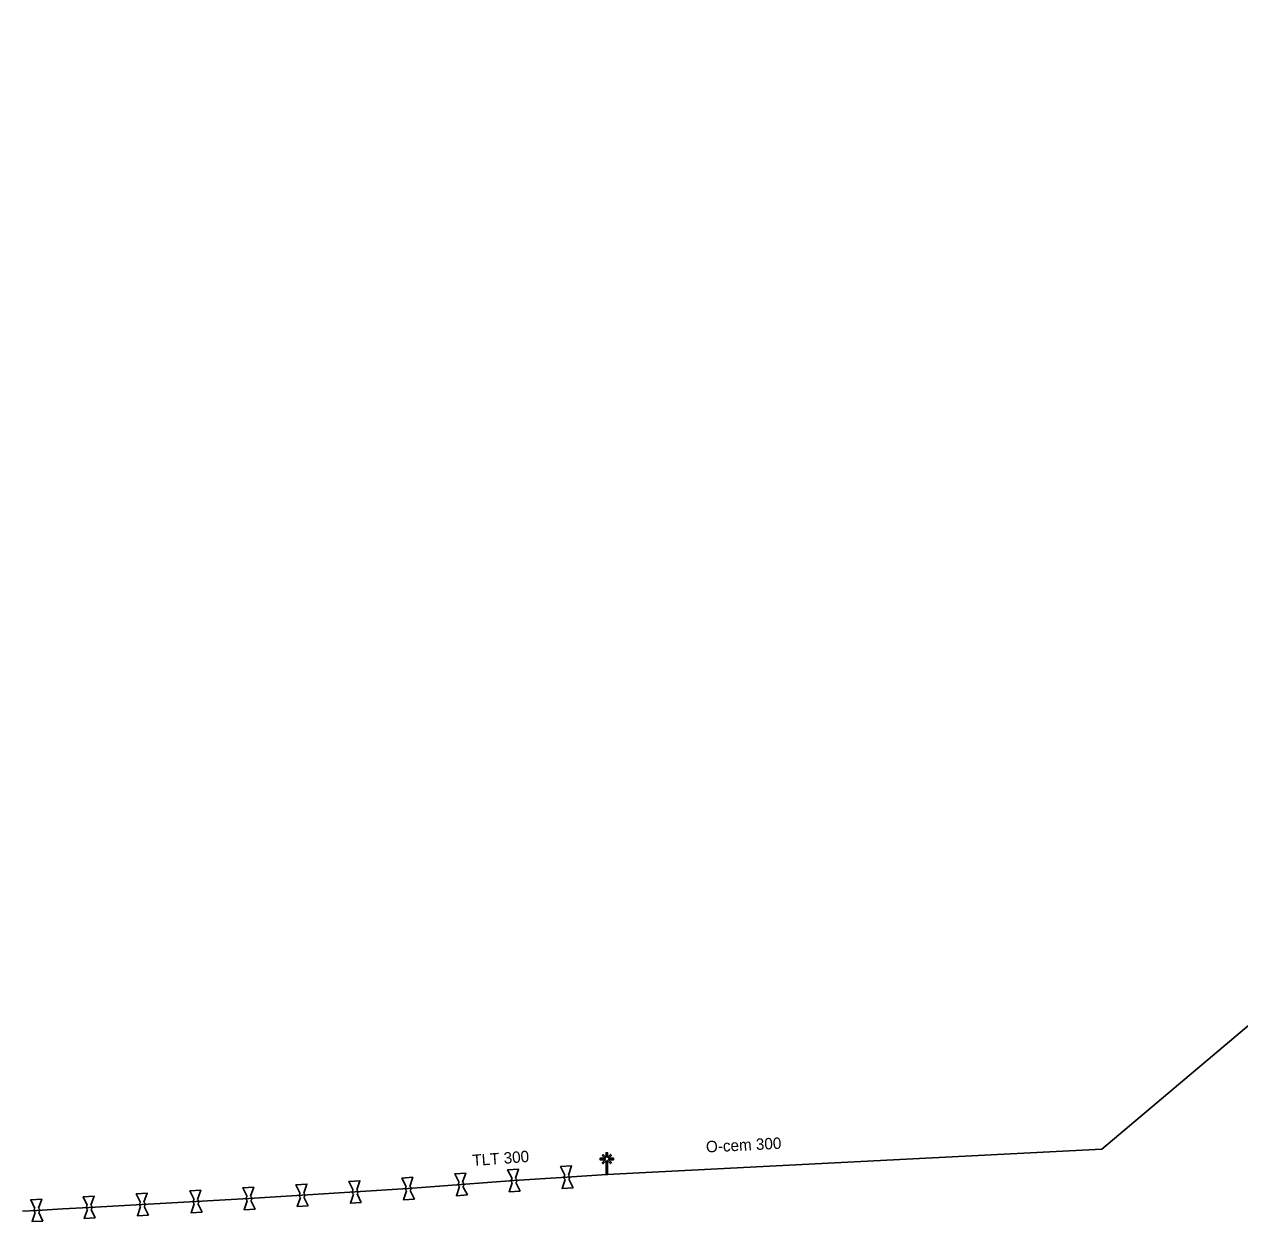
# Model space of a CAD drawing. Extents: x -638315 to -636370, y -1116147 to -1115110.
# Drawn here: x -636990.8 to -636852.3, y -1116147.3 to -1116010.8 of the extents above; entities that cross this region are included whole.
import ezdxf

# ---------------------------------------------------------------- set-up
doc = ezdxf.new("R2010")
doc.units = 0
for name, color, linetype in [('Default', 7, 'Continuous'), ('VP Lomový bod', 7, 'Continuous'), ('VP Změna materiálu', 7, 'Continuous'), ('VP Řad', 7, 'Continuous'), ('VP Řad - popis', 7, 'Continuous')]:
    doc.layers.add(name, color=color, linetype=linetype)

msp = doc.modelspace()

# ---------------------------------------------------------------- linework, layer by layer
at = {"layer": 'Default'}
for points in [[(-636941.24, -1116143.26), (-636941.28, -1116143.23), (-636941.31, -1116143.19), (-636941.36, -1116143.12), (-636941.36, -1116143.03), (-636941.37, -1116142.95), (-636941.33, -1116142.88), (-636941.31, -1116142.83), (-636941.27, -1116142.79)], [(-636940.87, -1116142.76), (-636940.82, -1116142.79), (-636940.79, -1116142.83), (-636940.75, -1116142.9), (-636940.74, -1116142.99), (-636940.73, -1116143.07), (-636940.77, -1116143.15), (-636940.79, -1116143.19), (-636940.83, -1116143.23)], [(-636935.21, -1116142.81), (-636935.25, -1116142.78), (-636935.28, -1116142.74), (-636935.33, -1116142.66), (-636935.33, -1116142.58), (-636935.34, -1116142.5), (-636935.3, -1116142.43), (-636935.28, -1116142.38), (-636935.24, -1116142.34)], [(-636934.83, -1116142.31), (-636934.79, -1116142.34), (-636934.76, -1116142.39), (-636934.71, -1116142.46), (-636934.71, -1116142.54), (-636934.7, -1116142.62), (-636934.74, -1116142.7), (-636934.76, -1116142.75), (-636934.8, -1116142.78)], [(-636929.19, -1116142.44), (-636929.23, -1116142.41), (-636929.26, -1116142.36), (-636929.31, -1116142.29), (-636929.31, -1116142.21), (-636929.32, -1116142.13), (-636929.28, -1116142.05), (-636929.26, -1116142), (-636929.22, -1116141.97)], [(-636928.81, -1116141.94), (-636928.77, -1116141.97), (-636928.74, -1116142.02), (-636928.69, -1116142.09), (-636928.69, -1116142.17), (-636928.68, -1116142.25), (-636928.72, -1116142.33), (-636928.74, -1116142.38), (-636928.78, -1116142.41)], [(-636965.42, -1116144.86), (-636965.46, -1116144.83), (-636965.49, -1116144.78), (-636965.54, -1116144.71), (-636965.54, -1116144.63), (-636965.55, -1116144.55), (-636965.51, -1116144.47), (-636965.49, -1116144.42), (-636965.45, -1116144.39)], [(-636965.04, -1116144.36), (-636965, -1116144.39), (-636964.97, -1116144.44), (-636964.92, -1116144.51), (-636964.92, -1116144.59), (-636964.91, -1116144.67), (-636964.95, -1116144.75), (-636964.97, -1116144.8), (-636965.01, -1116144.84)], [(-636959.37, -1116144.5), (-636959.41, -1116144.47), (-636959.44, -1116144.42), (-636959.49, -1116144.35), (-636959.49, -1116144.27), (-636959.5, -1116144.19), (-636959.46, -1116144.11), (-636959.44, -1116144.06), (-636959.4, -1116144.03)], [(-636958.99, -1116144), (-636958.95, -1116144.03), (-636958.92, -1116144.08), (-636958.87, -1116144.15), (-636958.87, -1116144.23), (-636958.86, -1116144.31), (-636958.9, -1116144.39), (-636958.92, -1116144.44), (-636958.96, -1116144.47)], [(-636953.32, -1116144.12), (-636953.36, -1116144.09), (-636953.39, -1116144.04), (-636953.44, -1116143.97), (-636953.44, -1116143.89), (-636953.45, -1116143.81), (-636953.41, -1116143.73), (-636953.39, -1116143.68), (-636953.35, -1116143.65)], [(-636952.94, -1116143.62), (-636952.9, -1116143.65), (-636952.87, -1116143.7), (-636952.82, -1116143.77), (-636952.82, -1116143.85), (-636952.81, -1116143.93), (-636952.85, -1116144.01), (-636952.87, -1116144.06), (-636952.91, -1116144.09)], [(-636947.27, -1116143.73), (-636947.31, -1116143.7), (-636947.34, -1116143.66), (-636947.39, -1116143.59), (-636947.39, -1116143.5), (-636947.4, -1116143.42), (-636947.36, -1116143.35), (-636947.34, -1116143.3), (-636947.3, -1116143.26)], [(-636946.9, -1116143.23), (-636946.85, -1116143.26), (-636946.82, -1116143.3), (-636946.77, -1116143.37), (-636946.77, -1116143.46), (-636946.76, -1116143.54), (-636946.8, -1116143.62), (-636946.82, -1116143.66), (-636946.86, -1116143.7)], [(-636989.6, -1116146.22), (-636989.64, -1116146.19), (-636989.67, -1116146.14), (-636989.72, -1116146.07), (-636989.72, -1116145.99), (-636989.73, -1116145.91), (-636989.69, -1116145.83), (-636989.67, -1116145.78), (-636989.63, -1116145.75)], [(-636989.22, -1116145.72), (-636989.18, -1116145.75), (-636989.15, -1116145.8), (-636989.1, -1116145.87), (-636989.1, -1116145.95), (-636989.09, -1116146.03), (-636989.13, -1116146.11), (-636989.15, -1116146.16), (-636989.19, -1116146.2)], [(-636983.63, -1116145.87), (-636983.67, -1116145.84), (-636983.7, -1116145.79), (-636983.75, -1116145.72), (-636983.75, -1116145.64), (-636983.76, -1116145.56), (-636983.72, -1116145.48), (-636983.69, -1116145.43), (-636983.66, -1116145.39)], [(-636983.25, -1116145.37), (-636983.21, -1116145.4), (-636983.18, -1116145.45), (-636983.13, -1116145.52), (-636983.13, -1116145.6), (-636983.12, -1116145.68), (-636983.16, -1116145.76), (-636983.19, -1116145.81), (-636983.22, -1116145.85)], [(-636977.58, -1116145.54), (-636977.62, -1116145.51), (-636977.65, -1116145.46), (-636977.7, -1116145.39), (-636977.7, -1116145.31), (-636977.71, -1116145.23), (-636977.67, -1116145.15), (-636977.64, -1116145.1), (-636977.61, -1116145.06)], [(-636977.2, -1116145.04), (-636977.16, -1116145.07), (-636977.13, -1116145.12), (-636977.08, -1116145.19), (-636977.08, -1116145.27), (-636977.07, -1116145.35), (-636977.11, -1116145.43), (-636977.14, -1116145.48), (-636977.17, -1116145.52)], [(-636971.46, -1116145.21), (-636971.5, -1116145.18), (-636971.53, -1116145.13), (-636971.58, -1116145.06), (-636971.58, -1116144.98), (-636971.59, -1116144.9), (-636971.55, -1116144.82), (-636971.53, -1116144.77), (-636971.49, -1116144.74)], [(-636971.08, -1116144.71), (-636971.04, -1116144.74), (-636971.01, -1116144.79), (-636970.96, -1116144.86), (-636970.96, -1116144.94), (-636970.95, -1116145.02), (-636970.99, -1116145.1), (-636971.01, -1116145.15), (-636971.05, -1116145.19)]]:
    msp.add_open_spline(points, degree=3, dxfattribs=at)
at = {"layer": 'VP Lomový bod'}
for points in [[(-636941.27, -1116142.79), (-636941.77, -1116141.81), (-636940.52, -1116141.72), (-636940.87, -1116142.76)], [(-636935.24, -1116142.34), (-636935.74, -1116141.36), (-636934.49, -1116141.27), (-636934.83, -1116142.31)], [(-636929.22, -1116141.97), (-636929.71, -1116140.98), (-636928.46, -1116140.9), (-636928.81, -1116141.94)], [(-636959.4, -1116144.03), (-636959.88, -1116143.04), (-636958.63, -1116142.96), (-636958.99, -1116144)], [(-636953.35, -1116143.65), (-636953.83, -1116142.66), (-636952.59, -1116142.58), (-636952.94, -1116143.62)], [(-636947.3, -1116143.26), (-636947.8, -1116142.28), (-636946.55, -1116142.19), (-636946.9, -1116143.23)], [(-636934.3, -1116143.76), (-636935.55, -1116143.85), (-636935.21, -1116142.81)], [(-636934.8, -1116142.78), (-636934.3, -1116143.76)], [(-636928.29, -1116143.4), (-636929.54, -1116143.48), (-636929.19, -1116142.44)], [(-636928.78, -1116142.41), (-636928.29, -1116143.4)], [(-636983.66, -1116145.39), (-636984.13, -1116144.41), (-636982.88, -1116144.34), (-636983.25, -1116145.37)], [(-636977.61, -1116145.06), (-636978.08, -1116144.08), (-636976.83, -1116144.01), (-636977.2, -1116145.04)], [(-636971.49, -1116144.74), (-636971.97, -1116143.75), (-636970.72, -1116143.68), (-636971.08, -1116144.71)], [(-636965.45, -1116144.39), (-636965.93, -1116143.4), (-636964.68, -1116143.33), (-636965.04, -1116144.36)], [(-636958.48, -1116145.46), (-636959.73, -1116145.54), (-636959.37, -1116144.5)], [(-636958.96, -1116144.47), (-636958.48, -1116145.46)], [(-636952.43, -1116145.08), (-636953.67, -1116145.16), (-636953.32, -1116144.12)], [(-636952.91, -1116144.09), (-636952.43, -1116145.08)], [(-636946.36, -1116144.68), (-636947.61, -1116144.77), (-636947.27, -1116143.73)], [(-636946.86, -1116143.7), (-636946.36, -1116144.68)], [(-636940.33, -1116144.21), (-636941.58, -1116144.3), (-636941.24, -1116143.26)], [(-636940.83, -1116143.23), (-636940.33, -1116144.21)], [(-636989.63, -1116145.75), (-636990.11, -1116144.76), (-636988.86, -1116144.69), (-636989.22, -1116145.72)], [(-636982.75, -1116146.83), (-636984, -1116146.9), (-636983.63, -1116145.87)], [(-636983.22, -1116145.85), (-636982.75, -1116146.83)], [(-636976.7, -1116146.5), (-636977.95, -1116146.57), (-636977.58, -1116145.54)], [(-636977.17, -1116145.52), (-636976.7, -1116146.5)], [(-636970.57, -1116146.17), (-636971.82, -1116146.24), (-636971.46, -1116145.21)], [(-636971.05, -1116145.19), (-636970.57, -1116146.17)], [(-636964.53, -1116145.82), (-636965.78, -1116145.89), (-636965.42, -1116144.86)], [(-636965.01, -1116144.84), (-636964.53, -1116145.82)], [(-636988.71, -1116147.18), (-636989.96, -1116147.25), (-636989.6, -1116146.22)], [(-636989.19, -1116146.2), (-636988.71, -1116147.18)]]:
    msp.add_lwpolyline(points, dxfattribs=at)
at = {"layer": 'VP Změna materiálu'}
msp.add_lwpolyline([(-636924.51, -1116139.93), (-636924.51, -1116139.39), (-636924.35, -1116139.39), (-636924.35, -1116139.92), (-636924.02, -1116139.59), (-636923.91, -1116139.7), (-636924.24, -1116140.03), (-636923.66, -1116140.03), (-636923.66, -1116140.19), (-636924.25, -1116140.19), (-636923.91, -1116140.52), (-636924.02, -1116140.63), (-636924.35, -1116140.31), (-636924.35, -1116141.89), (-636924.51, -1116141.89), (-636924.51, -1116140.3), (-636924.84, -1116140.64), (-636924.95, -1116140.53), (-636924.61, -1116140.19), (-636925.2, -1116140.19), (-636925.2, -1116140.03), (-636924.62, -1116140.03), (-636924.95, -1116139.7), (-636924.84, -1116139.6), (-636924.51, -1116139.93)], dxfattribs=at)
at = {"layer": 'VP Řad'}
for points in [[(-636924.43, -1116141.89), (-636868.01, -1116138.98), (-636850.3, -1116124.04), (-636727.75, -1116091.42), (-636718.57, -1116087.25), (-636590.7, -1116029.14), (-636489.94, -1115968.84), (-636407.46, -1115921.07), (-636400.41, -1115921.47)], [(-636924.43, -1116141.89), (-636929, -1116142.19), (-636935.02, -1116142.56), (-636941.05, -1116143.01), (-636947.08, -1116143.48), (-636953.13, -1116143.87), (-636959.18, -1116144.25), (-636965.23, -1116144.61), (-636971.27, -1116144.96), (-636977.39, -1116145.29), (-636983.44, -1116145.62), (-636986.43, -1116145.79), (-636989.41, -1116145.97), (-636991.04, -1116146.05)]]:
    msp.add_lwpolyline(points, dxfattribs=at)

# ---------------------------------------------------------------- texts
at = {"layer": 'VP Řad - popis'}
for s, rotation, p in [('O-cem 300', 2.8724, (-636913.1, -1116139.37)), ('TLT 300', 4.2679, (-636939.71, -1116140.92))]:
    msp.add_text(s, height=1.3, rotation=rotation, dxfattribs=at).set_placement(p)

doc.saveas('drawing.dxf')
